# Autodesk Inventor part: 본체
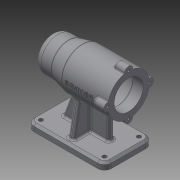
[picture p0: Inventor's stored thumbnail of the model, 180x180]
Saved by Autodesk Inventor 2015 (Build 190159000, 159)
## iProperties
Created: 2019-07
Part Number: 본체
Material: 일반
Document SubType Name: Modeling
Designer: cad-11
Density: 1 g/cm^3
Appearance: 기본값
Author: cad-11
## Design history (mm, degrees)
sketch "스케치2"
  geometry: L1 (-56, 35)-(56, 35); L2 (56, 35)-(56, -35); L3 (56, -35)-(-56, -35); L4 (-56, -35)-(-56, 35); L5 (-56, 35)-(56, -35); L6 (56, 35)-(-56, -35); 1 further point
  constraints: 12 end point, 2 midpoint, 2 parallel, 1 horizontal, 1 perpendicular
  dimensions: "d4" = 112 distance of L1.start L1.end; "d5" = 70 distance of L1.end L2.end
extrude "돌출2" new body sketch "스케치2" distance "d6" = 10; taper "d7" = 0 deg
fillet "모깎기1" dims "d8" = 10
sketch "스케치3"
  geometry: A1 r 10 centre (-46, 25) between (-46, 35) and (-56, 25) reference; A2 r 10 centre (-46, -25) between (-56, -25) and (-46, -35) reference; A3 r 10 centre (46, -25) between (46, -35) and (56, -25) reference; A4 r 10 centre (46, 25) between (56, 25) and (46, 35) reference; 1 further point
hole "구멍1" sketch "스케치3" at (-46, 25), (-46, -25), (46, -25), (46, 25) diameter "d9" = 6; stored, may be unused: countersink angle "d13" = 90 deg, drill point angle "d15" = 118 deg; dims "d10" = 8, "d11" = 4, "d12" = 2, "d14" = 11
sketch "스케치4"
  geometry: L1 (-56, 25)-(-56, -25) reference; L2 (-46, -35)-(46, -35) reference; L3 (56, -25)-(56, 25) reference; L4 (46, 35)-(-46, 35) reference; L5 (-36, 4)-(31, 4); L6 (31, 4)-(31, -4); L7 (31, -4)-(-36, -4); L8 (-36, -4)-(-36, 4); L9 (-4, 28)-(4, 28); L10 (4, 28)-(4, -28); L11 (4, -28)-(-4, -28); L12 (-4, -28)-(-4, 28); 3 further points
  constraints: 16 end point, 4 parallel, 2 horizontal, 2 midpoint, 2 perpendicular, 1 horizontal alignment, 1 vertical alignment
  dimensions: "d16" = 25 distance between parallel lines of L3 L6; "d17" = 8 distance between parallel lines of L7 L5; "d18" = 20 distance between parallel lines of L1 L8; "d19" = 4 distance from line of point (0, 0) L12; "d20" = 7 distance between parallel lines of L2 L11; "d21" = 7 distance between parallel lines of L4 L9
extrude "돌출3" join sketch "스케치4" distance "d22" = 70; taper "d23" = 0 deg
feature "면 기울기1" dims angle "d24" = 10 deg
feature "면 기울기2" dims angle "d25" = 10 deg
feature "면 기울기3" dims angle "d26" = 20 deg
sketch "스케치15"
  geometry: L1 (56, 10)-(56, 0) reference; L2 (56, 0)-(-56, 0) reference; L3 (-56, 0)-(-56, 10) reference; L4 (-56, 10)-(-31, 10) reference; L5 (-31, 10)-(-31, 80) reference; L6 (-31, 80)-(10.522, 80) reference; L7 (10.522, 80)-(36, 10) reference; L8 (36, 10)-(56, 10) reference; L9 (56, 80)-(-56, 80); L10 (-56, 80)-(-56, 110); L11 (-56, 110)-(11, 110); L12 (11, 110)-(31, 105); L13 (31, 105)-(56, 105); L14 (56, 105)-(56, 80); 3 further points
  constraints: 12 end point, 3 perpendicular, 2 midpoint, 1 collinear, 1 horizontal, 1 parallel, 1 vertical alignment
  dimensions: "d39" = 25 distance of L13.end L9.start; "d40" = 30 distance between parallel lines of L9 L11; "d41" = 25 distance from line of L12.end L14; "d42" = 45 distance from line of L11.end L14; "d43" = 112 distance between parallel lines of L10 L14
revolve "회전1" sketch "스케치15" stored, may be unused: angle "d44" = 90 deg
sketch "스케치17"
  geometry: C1 r 6 at (0, 30); 2 further points
  constraints: 2 vertical alignment, 1 centre point, 1 other
  dimensions: "d45" = 12 diameter of C1
extrude "돌출8" join sketch "스케치17" distance "d46" = 16; taper "d47" = 0 deg
fillet "모깎기2" dims "d51" = 3
fillet "모깎기3" dims "d52" = 3
fillet "모깎기4" dims "d53" = 1
sketch "스케치18"
  geometry: A1 r 6 centre (-60, 0) between (-60.171, 5.998) and (-60.171, -5.998) reference; 1 further point
hole "구멍2" sketch "스케치18" at (-60, 0) diameter "d54" = 3.242; stored, may be unused: countersink angle "d58" = 90 deg, drill point angle "d60" = 118 deg; dims "d55" = 8, "d56" = 4, "d57" = 2, "d59" = 11
sketch "스케치19"
  geometry: C1 r 21 at (-30, 0); A1 r 30 centre (-30, 0) between (-59.226, -6.771) and (-36.771, -29.226) reference; 1 further point
  constraints: 1 centre point, 1 coincident
  dimensions: "d64" = 42 diameter of C1
extrude "돌출9" cut sketch "스케치19" distance "d65" = 15; taper "d66" = 0 deg
sketch "스케치20"
  geometry: C1 r 21 at (0, 0) reference; C2 r 24 at (0, 0); 1 further point
  constraints: 1 centre point, 1 coincident
  dimensions: "d67" = 48 diameter of C2
extrude "돌출10" cut sketch "스케치20" distance "d68" = 54; taper "d69" = 0 deg
sketch "스케치21"
  geometry: C1 r 24 at (0, 0) reference; C2 r 21 at (0, 0); 1 further point
  constraints: 1 centre point, 1 coincident
  dimensions: "d70" = 42 diameter of C2
extrude "돌출11" cut sketch "스케치21" distance "d71" = 12; taper "d72" = 0 deg
sketch "스케치22"
  geometry: C1 r 21 at (0, 0) reference; C2 r 17.5 at (0, 0); 1 further point
  constraints: 1 centre point, 1 coincident
  dimensions: "d73" = 35 diameter of C2
extrude "돌출12" cut sketch "스케치22" distance "d74" = 18; taper "d75" = 0 deg
sketch "스케치23"
  geometry: C1 r 17.5 at (0, 0) reference; C2 r 16 at (0, 0); 1 further point
  constraints: 1 centre point, 1 coincident
  dimensions: "d76" = 32 diameter of C2
extrude "돌출13" cut sketch "스케치23" distance "d77" = 4; taper "d78" = 0 deg
sketch "스케치24"
  geometry: C1 r 16 at (0, 0) reference; C2 r 10.5 at (0, 0); 1 further point
  constraints: 1 centre point, 1 coincident
  dimensions: "d79" = 21 diameter of C2
extrude "돌출14" cut sketch "스케치24" distance "d80" = 3; taper "d81" = 0 deg
fillet "모깎기5" dims "d82" = 3
fillet "모깎기6" dims "d83" = 10
fillet "모깎기7" dims "d84" = 3
fillet "모깎기8" dims "d85" = 3
fillet "모깎기9" dims "d86" = 3
fillet "모깎기10" dims "d87" = 3
fillet "모깎기11" dims "d88" = 3
chamfer "모따기1" distance "d89" = 3; stored, may be unused: second distance "d90" = 2, angle "d91" = 45 deg
fillet "모깎기12" dims "d92" = 3
fillet "모깎기13" dims "d93" = 0.3
node "작업 평면1"
sketch "스케치25"
  geometry: L1 (33.5, 6.771)-(33.5, 29.226) reference; L2 (33.5, 5.998)-(33.5, -5.998) reference; 3 further points
  constraints: 1 horizontal alignment, 1 midpoint, 1 other
  dimensions: "d98" = 42 distance from line of L1 point (-8.5, 0)
feature "엠보싱1" sketch "스케치25" dims "d95" = 0.5, "d96" = 0
node "솔리드2"
pattern_circular "원형 패턴1" dims angle "d49" = 360 deg
pattern_circular "원형 패턴2" dims angle "d62" = 360 deg
node "절단 모서리 투영6"
